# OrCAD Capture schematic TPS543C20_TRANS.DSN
size D; title: TPS543C20 4 Vin to 16 Vin, 40-A Stackable, Synchronous Step-; rev: 1.0; note: Datasheet: SLUSCD4    EVM: SLUUBK7; note: Synchronous Step Down Converter
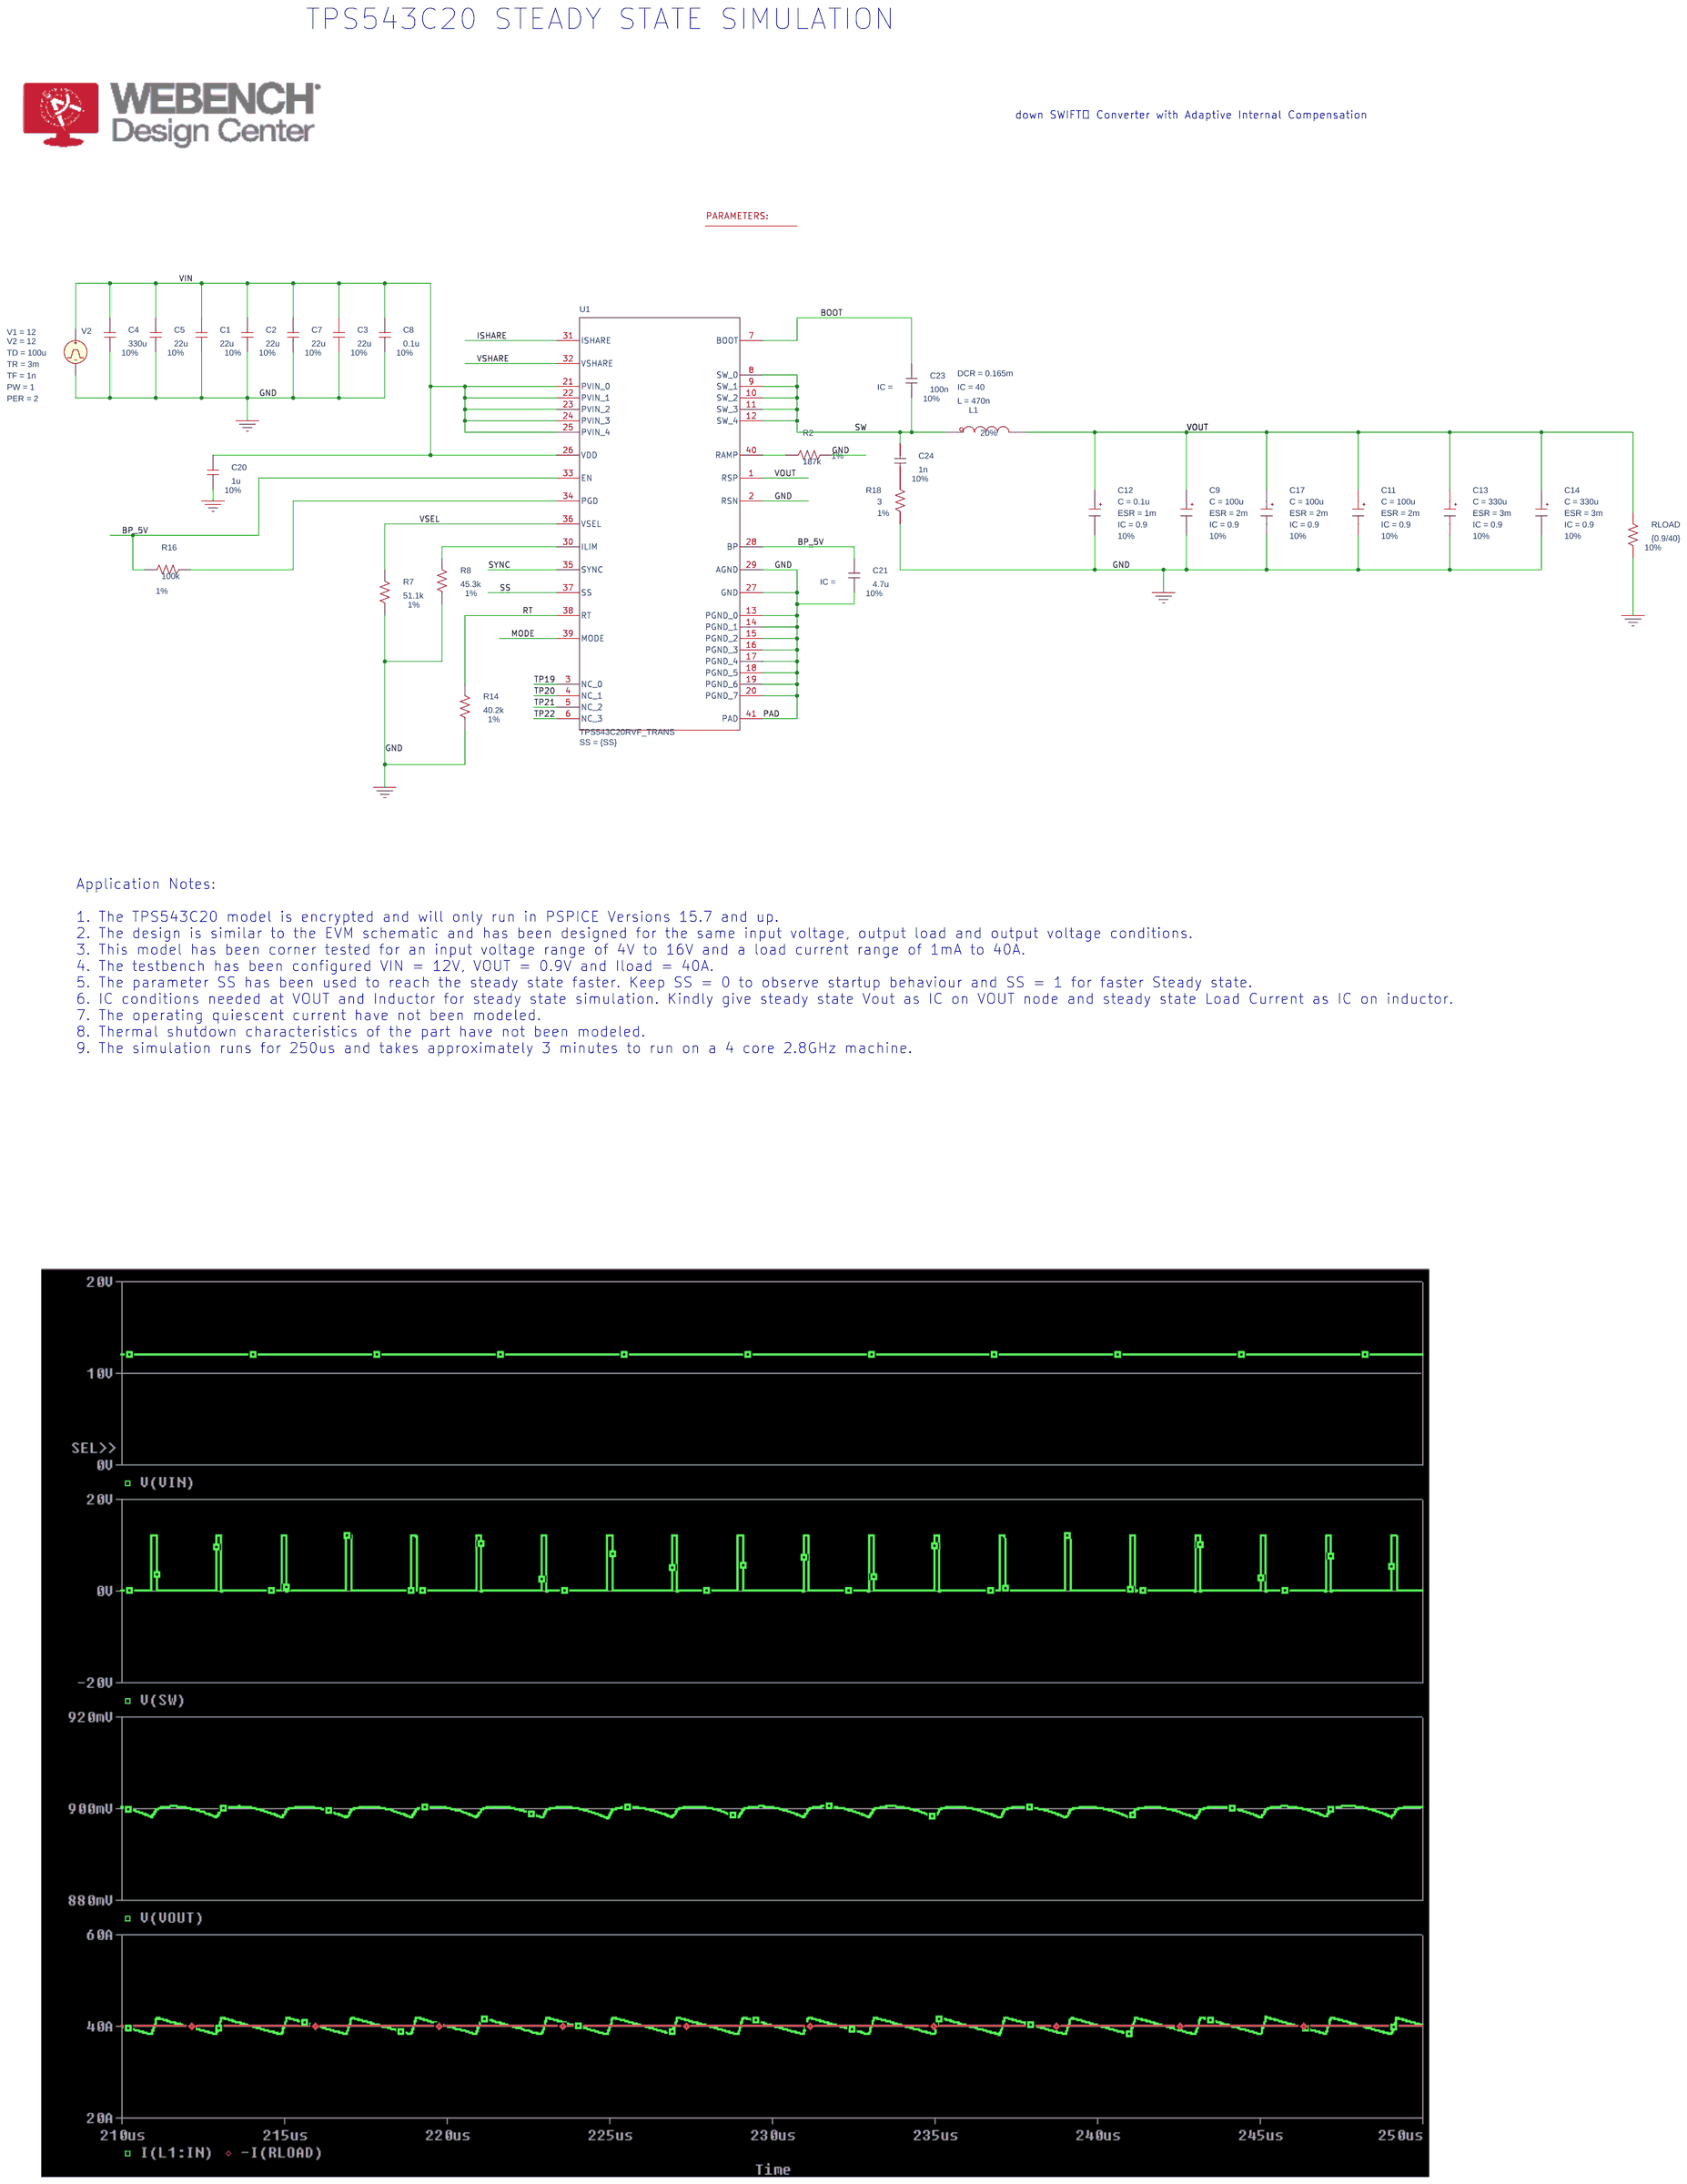
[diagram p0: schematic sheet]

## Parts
1  PARAM
C1  22u  [RAD/CK05]
C2  22u  [RAD/CK05]
C3  22u  [RAD/CK05]
C4  330u  [RAD/CK05]
C5  22u  [RAD/CK05]
C7  22u  [RAD/CK05]
C8  0.1u  [RAD/CK05]
C9  CESR
C11  CESR
C12  CESR
C13  CESR
C14  CESR
C17  CESR
C20  1u  [RAD/CK05]
C21  4.7u  [RAD/CK05]
C23  100n  [RAD/CK05]
C24  1n  [RAD/CK05]
L1  LDCR
R2  187k  [AX/RC05]
R7  51.1k  [AX/RC05]
R8  45.3k  [AX/RC05]
R14  40.2k  [AX/RC05]
R16  100k  [AX/RC05]
R18  3  [AX/RC05]
RLOAD  {0.9/40}  [AX/RC05]
U1  TPS543C20RVF_TRANS  [RVF0040A]
V2  VPULSE

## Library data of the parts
1 = PARAM
C1-C5 C7 C8 C20 C21 C23 C24 = C: TOLERANCE: 10%
C9 C11 C17 = CESR_0: C: 100u; ESR: 2m; IC: 0.9; PSpiceTemplate: X^@REFDES %IN %OUT @MODEL PARAMS:  ?C|C=@C||C=100u|  ?ESR|ESR=@ESR||ESR=0.01| ?X|X=@X||X=2|  ?IC|IC=@IC||IC=2|; TOLERANCE: 10%; X: 1
C12 = CESR_0: C: 0.1u; ESR: 1m; IC: 0.9; PSpiceTemplate: X^@REFDES %IN %OUT @MODEL PARAMS:  ?C|C=@C||C=100u|  ?ESR|ESR=@ESR||ESR=0.01| ?X|X=@X||X=2|  ?IC|IC=@IC||IC=2|; TOLERANCE: 10%; X: 1
C13 C14 = CESR_0: C: 330u; ESR: 3m; IC: 0.9; PSpiceTemplate: X^@REFDES %IN %OUT @MODEL PARAMS:  ?C|C=@C||C=100u|  ?ESR|ESR=@ESR||ESR=0.01| ?X|X=@X||X=2|  ?IC|IC=@IC||IC=2|; TOLERANCE: 10%; X: 1
L1 = LDCR_0: DCR: 0.165m; IC: 40; L: 470n; PSpiceTemplate: X^@REFDES %IN %OUT @MODEL PARAMS:  ?L|L=@L||L=1u|  ?DCR|DCR=@DCR||DCR=0.01| ?IC|IC=@IC||IC=0|; TOLERANCE: 20%
R2 R7 R8 R14 R16 R18 = R: TOLERANCE: 1%
RLOAD = R: TOLERANCE: 10%
U1 = TPS543C20RVF_TRANS: SS: {SS}
V2 = VPULSE: PER: 2; PW: 1; TD: 100u; TF: 1n; TR: 3m; V1: 12; V2: 12

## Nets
VIN: C1.2 C2.2 C3.2 C4.2 C5.2 C7.2 C8.2 C20.2 U1.21(PVIN_0) U1.22(PVIN_1) U1.23(PVIN_2) U1.24(PVIN_3) U1.25(PVIN_4) U1.26(VDD) V2.1(+)
0: C1.1 C2.1 C3.1 C4.1 C5.1 C7.1 C8.1 C9.3(OUT) C11.3(OUT) C12.3(OUT) C13.3(OUT) C14.3(OUT) C17.3(OUT) C20.1 C21.1 R2.2 R7.1 R8.1 R14.1 R18.1 RLOAD.1 U1.2(RSN) U1.13(PGND_0) U1.14(PGND_1) U1.15(PGND_2) U1.16(PGND_3) U1.17(PGND_4) U1.18(PGND_5) U1.19(PGND_6) U1.20(PGND_7) U1.27(GND) U1.29(AGND) U1.41(PAD) V2.2(-)
BOOT: C23.2 U1.7(BOOT)
BP_5V: C21.2 R16.1 U1.28(BP) U1.33(EN)
ISHARE: U1.31(ISHARE)
MODE: U1.39(MODE)
RT: R14.2 U1.38(RT)
SS: U1.37(SS)
SW: C23.1 C24.1 L1.1(IN) U1.8(SW_0) U1.9(SW_1) U1.10(SW_2) U1.11(SW_3) U1.12(SW_4)
SYNC: U1.35(SYNC)
TP19: U1.3(NC_0)
TP20: U1.4(NC_1)
TP21: U1.5(NC_2)
TP22: U1.6(NC_3)
VOUT: C9.1(IN) C11.1(IN) C12.1(IN) C13.1(IN) C14.1(IN) C17.1(IN) L1.3(OUT) RLOAD.2 U1.1(RSP)
VSEL: R7.2 U1.36(VSEL)
VSHARE: U1.32(VSHARE)
N16773006: R16.2 U1.34(PGD)
N16782591: R8.2 U1.30(ILIM)
N16794010: R2.1 U1.40(RAMP)
N16836383: C24.2 R18.2

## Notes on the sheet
- TPS543C20 STEADY STATE SIMULATION
- down SWIFT™ Converter with Adaptive Internal Compensation
- Application Notes:
  1. The TPS543C20 model is encrypted and will only run in PSPICE Versions 15.7 and up.
  2. The design is similar to the EVM schematic and has been designed for the same input voltage, output load and output voltage conditions.
  3. This model has been corner tested for an input voltage range of 4V to 16V and a load current range of 1mA to 40A.
  4. The testbench has been configured VIN = 12V, VOUT = 0.9V and Iload = 40A.
  5. The parameter SS has been used to reach the steady state faster. Keep SS = 0 to observe startup behaviour and SS = 1 for faster Steady state.
  6. IC conditions needed at VOUT and Inductor for steady state simulation. Kindly give steady state Vout as IC on VOUT node and steady state Load Current as IC on inductor.
  7. The operating quiescent current have not been modeled.
  8. Thermal shutdown characteristics of the part have not been modeled.
  9. The simulation runs for 250us and takes approximately 3 minutes to run on a 4 core 2.8GHz machine.
